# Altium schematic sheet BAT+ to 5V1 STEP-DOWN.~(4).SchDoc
size A3; SheetNumber: 11; SheetTotal: 15
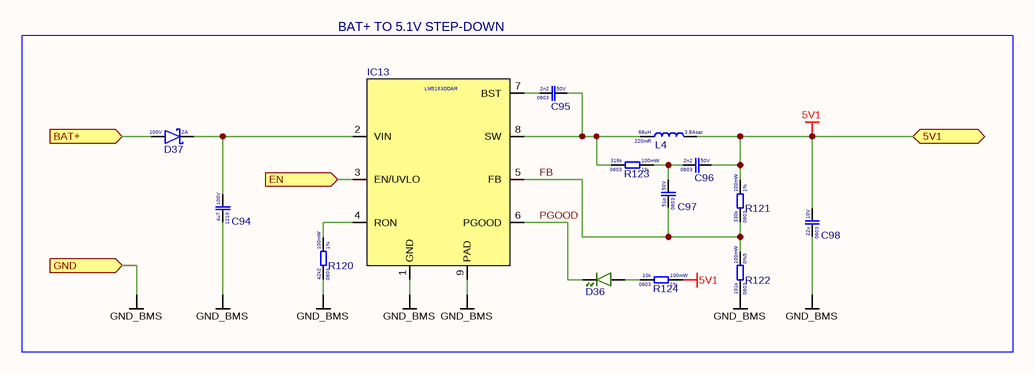
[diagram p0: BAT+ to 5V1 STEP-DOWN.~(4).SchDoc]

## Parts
C94  Voltage Rating: 100V  Case Code (Imperial): 1210  Capacitance: 4u7  [CAP_1210]  (hidden comment: HMK325C7475KN-TE)
C95  Voltage Rating: 50V  Case Code (Imperial): 0603  Capacitance: 2n2  [CAP 0603]  (hidden comment: 0603B222K500NT)
C96  Voltage Rating: 50V  Case Code (Imperial): 0603  Capacitance: 2n2  [CAP 0603]  (hidden comment: 0603B222K500NT)
C97  Voltage Rating: 50V  Case Code (Imperial): 0603  Capacitance: 51p  [CAP 0603]  (hidden comment: CC0603JRNPO9BN510)
C98  Voltage Rating: 10V  Case Code (Imperial): 0603  Capacitance: 22u  [CAP 0603]  (hidden comment: CGA0603X5R226M100JT)
D36  PSC-1608U52GC-G4  [DIODE_0603_GREEN]  (value not drawn)
D37  Forward Current: 2A  Reverse Voltage: 100V  [SMAF]  (hidden comment: SS210F)
IC13  LM5163DDAR  [ESOP-8]
L4  Resistance: 220mR  Saturation current: 3.8Asat  Inductance: 68uH  [IND 11.5x10mm]  (hidden comment: SMMS1040-680MT)
R120  Resistance Tolerance: 1%  Resistance: 42k2  Power Rating: 100mW  Case Code (Imperial): 0603  [RES_0603]  (hidden comment: 0603WAF4222T5E)
R121  Resistance Tolerance: 1%  Resistance: 330k  Power Rating: 100mW  Case Code (Imperial): 0603  [RES_0603]  (hidden comment: 0603WAF3303T5E)
R122  Resistance Tolerance: 0%5  Resistance: 101k  Power Rating: 100mW  Case Code (Imperial): 0603  [RES_0603]  (hidden comment: RT0603DRE07101KL)
R123  Resistance Tolerance: 1%  Resistance: 316k  Power Rating: 100mW  Case Code (Imperial): 0603  [RES_0603]  (hidden comment: 0603WAF3163T5E)
R124  Resistance Tolerance: 1%  Resistance: 10k  Power Rating: 100mW  Case Code (Imperial): 0603  [RES_0603]  (hidden comment: 0603WAF1002T5E)

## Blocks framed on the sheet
BAT+ TO 5.1V STEP-DOWN: C94-C98 D36 D37 IC13 L4 R120-R124

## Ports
5V1 (bidir, see BMS[4B]), BAT+ (in, see BMS[4B], BMS[1A], BQ34Z100 FUEL GAUGE[3A], BQ76952 BMS[1A], ESD battery side[5A]), EN (in, see BMS[4B]), GND (in, see BMS[4B], 5V to 3V3 LDO[3B], BQ34Z100 FUEL GAUGE[3C], BQ76952 BMS[1D], MCU[1C])

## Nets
5V1: C96.2 C98.2 L4.2 R121.2 R124.2 ; port 5V1
GND_BMS: C94.1 C98.1 IC13.1(GND) IC13.9(PAD) R120.1 R122.1 ; port GND
BAT+: D37.A ; port BAT+
EN: IC13.3(EN/UVLO) ; port EN
FB: C97.1 IC13.5(FB) R121.1 R122.2
PGOOD: D36.K IC13.6(PGOOD)
NetC94_2: C94.2 D37.K IC13.2(VIN)
NetC95_1: C95.1 IC13.7(BST)
NetC95_2: C95.2 IC13.8(SW) L4.1 R123.1
NetC96_1: C96.1 C97.2 R123.2
NetD36_A: D36.A R124.1
NetIC13_4: IC13.4(RON) R120.2

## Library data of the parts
C94 = HMK325C7475KN-TE: Cap 4.7uF 100V 1210 X7R; Manufacturer: Taiyo Yuden
C95 C96 = 0603B222K500NT: Cap 2n2F 50V 0603 X7R; Manufacturer: FH
C97 = CC0603JRNPO9BN510: Cap 51pF 50V 0603 NP0; Manufacturer: Yageo
C98 = CGA0603X5R226M100JT: Cap 22uF 10V 0603 X5R; Manufacturer: HRE
D36 = PSC-1608U52GC-G4: LED Green 0603 20mA; Manufacturer: HONGLITRONIC
D37 = SS210F: Schottky 100V 2A 850mVf SMAF; Manufacturer: GOODWORK
IC13 = LM5163DDAR: DCDC Step-down Converter 9~100Vin 0.5Aout; Manufacturer: Texas Instruments
L4 = SMMS1040-680MT: Inductor 68uH 3.8A 220mR SMD 11.5x10mm; Manufacturer: SXN
R120 = 0603WAF4222T5E: Res 42k2 0603 1% 100mW 75V; Manufacturer: Uni-Royal
R121 = 0603WAF3303T5E: Res 330k 0603 1% 100mW 75V; Manufacturer: Uni-Royal
R122 = RT0603DRE07101KL: Res 101k 0603 0.5% 100mW 75V; Manufacturer: YAGEO
R123 = 0603WAF3163T5E: Res 316k 0603 1% 100mW 75V; Manufacturer: Uni-Royal
R124 = 0603WAF1002T5E: Res 10k 0603 1% 100mW 75V; Manufacturer: Uni-Royal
